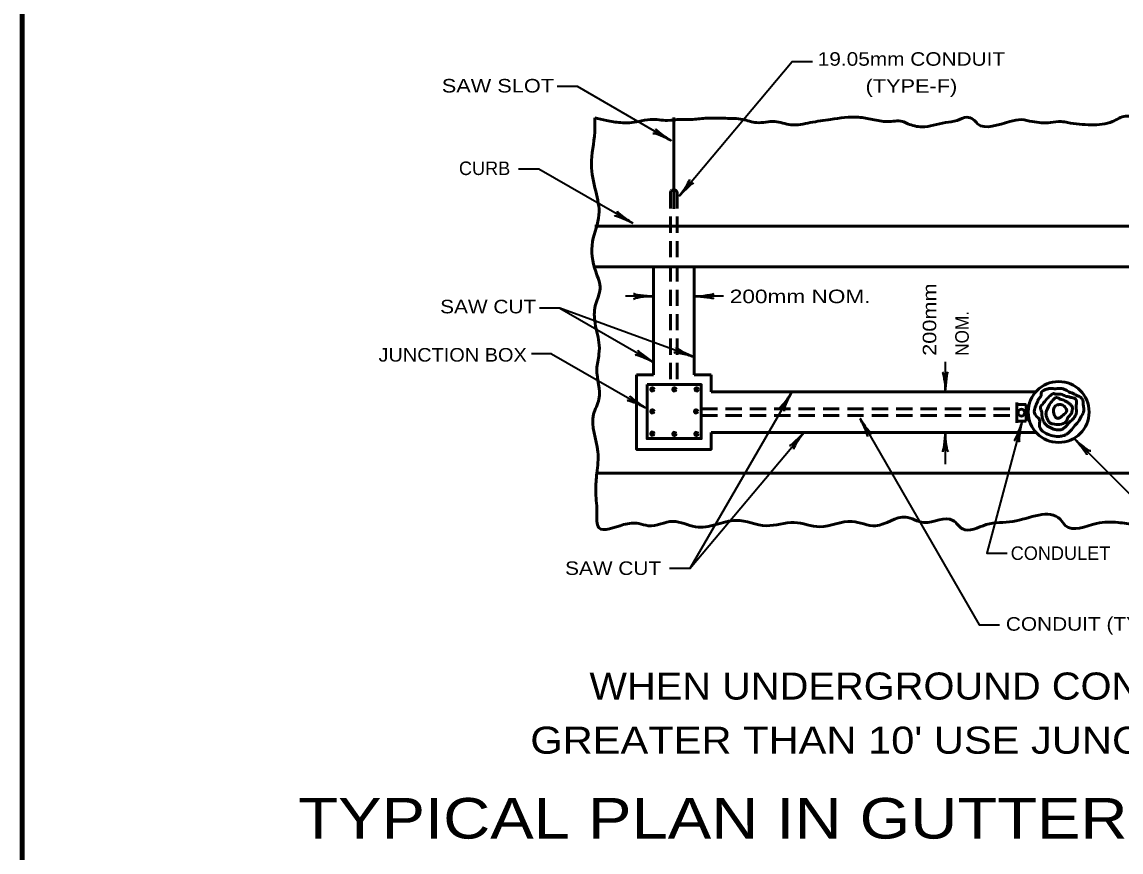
# Model space of a CAD drawing. Extents: x -90 to 623, y -379 to 75.
# Drawn here: x -42.6 to 119.8, y -254.8 to -132.1 of the extents above; entities that cross this region are included whole.
import ezdxf
from ezdxf.enums import TextEntityAlignment as Align

# ---------------------------------------------------------------- set-up
doc = ezdxf.new("R2010")
doc.units = 0
doc.header["$LTSCALE"] = 0.8
doc.linetypes.add('LONG_DASHED', pattern=[7.5, 6, -1.5])
doc.linetypes.add('MEDIUM_DASHED', pattern=[4.5, 3, -1.5])
doc.layers.add('1', color=7, linetype='Continuous', lineweight=35)

msp = doc.modelspace()

# ---------------------------------------------------------------- linework, layer by layer
at = {"layer": '1', "lineweight": 53}
for p, q in [((53.7427, -159.7717), (53.7427, -146.2717)), ((42.0595, -162.3067), (142.0595, -162.3067)), ((42.0595, -168.3067), (142.0595, -168.3067)), ((50.7427, -168.3067), (50.7427, -184.3067)), ((56.7427, -168.3067), (56.7427, -184.3067)), ((50.7427, -184.3067), (48.2427, -184.3067)), ((56.7427, -184.3067), (59.2427, -184.3067)), ((59.2427, -184.3067), (59.2427, -186.8067)), ((59.2427, -186.8067), (107.227, -186.8067)), ((104.3797, -188.6473), (105.8, -188.6473)), ((104.418, -188.3786), (104.418, -191.3786)), ((105.8, -188.6473), (105.8, -191.1473)), ((104.3797, -191.1473), (105.8, -191.1473)), ((59.2427, -192.8067), (93.8582, -192.8067)), ((93.779, -192.8067), (107.2712, -192.8067)), ((42.3769, -198.8067), (142.0708, -198.8067))]:
    msp.add_line(p, q, dxfattribs=at)
at = {"layer": '1', "linetype": 'MEDIUM_DASHED', "lineweight": 53}
for p, q in [((53.2427, -157.3067), (53.2427, -185.7174)), ((54.2427, -157.3067), (54.2427, -185.7174)), ((57.7928, -189.3067), (104.3989, -189.3067)), ((57.7928, -190.3067), (104.4088, -190.3067))]:
    msp.add_line(p, q, dxfattribs=at)
at = {"layer": '1'}
for p, q in [((50.6812, -172.6817), (46.602, -172.6817)), ((61.102, -172.6817), (56.7814, -172.6817)), ((36.8893, -174.4334), (33.8893, -174.4334)), ((35.701, -181.1674), (32.701, -181.1674)), ((35.701, -181.1674), (49.5574, -189.1674)), ((93.8582, -182.3864), (93.8582, -186.7438)), ((93.8582, -192.7647), (93.8582, -197.5024)), ((56.1208, -212.9046), (53.1208, -212.9046))]:
    msp.add_line(p, q, dxfattribs=at)
at = {"layer": '1', "lineweight": 158}
msp.add_lwpolyline([(617.1938, 69.4188), (-42.5562, 69.3355), (-42.4728, -368.9978)], dxfattribs=at)
at = {"layer": '1'}
for points in [[(54.5286, -157.8822), (71.241, -137.9651), (74.241, -137.9651)], [(53.3747, -149.6886), (39.5183, -141.6886), (36.5183, -141.6886)], [(47.6707, -161.889), (33.8143, -153.889), (30.8142, -153.889)], [(56.6229, -181.6158), (36.8893, -174.4334), (50.7458, -182.4334)], [(71.1208, -186.9238), (56.1208, -212.9046), (72.9849, -192.8067)], [(81.2615, -190.7265), (98.8817, -221.2457), (101.8817, -221.2457)], [(105.1616, -191.3462), (99.9852, -210.6647), (102.9852, -210.6647)], [(113.0107, -193.8116), (129.4815, -210.2824), (132.4815, -210.2824)]]:
    msp.add_lwpolyline(points, dxfattribs=at)
at = {"layer": '1', "lineweight": 53}
msp.add_lwpolyline([(48.2427, -184.3067), (48.2427, -195.3067), (59.2427, -195.3067), (59.2427, -192.8067)], dxfattribs=at)
msp.add_lwpolyline([(49.7928, -185.7174), (57.7928, -185.7174), (57.7928, -193.7174), (49.7928, -193.7174)], close=True, dxfattribs=at)
for centre, radius in [((50.5838, -186.4463), 0.25), ((53.8318, -186.4463), 0.25), ((57.1194, -186.4463), 0.25), ((110.6031, -189.7819), 4.5), ((50.5838, -189.6942), 0.25), ((57.0402, -189.6942), 0.25), ((105.1089, -189.8757), 0.5), ((50.5838, -192.9818), 0.25), ((53.8318, -193.0215), 0.25), ((57.0797, -193.0215), 0.25)]:
    msp.add_circle(centre, radius, dxfattribs=at)
at = {"layer": '1', "linetype": 'LONG_DASHED', "lineweight": 53}
msp.add_arc((53.7427, -157.4507), 0.5203, 16.07383, 163.92617, dxfattribs=at)
at = {"layer": '1', "lineweight": 40}
for centre, major_axis, ratio, start_param, end_param in [((52.2916, -149.3823), (1.6245, -0.7576), 0.122415, 0.89635335, 3.14159265), ((52.2916, -149.3823), (1.6245, -0.7576), 0.122415, 0.89635335, 3.14159265), ((52.5102, -148.9451), (1.4333, -1.0303), 0.07063, 3.14071475, 5.41810995), ((52.5102, -148.9451), (1.4333, -1.0303), 0.07063, 3.14071475, 5.41810995), ((55.0183, -156.8687), (-1.0282, -1.4683), 0.122415, 0.89635335, 3.14159265), ((55.0183, -156.8687), (-1.0282, -1.4683), 0.122415, 0.89635335, 3.14159265), ((55.4109, -157.1599), (1.2636, 1.2326), 0.07063, 6.28230741, 8.55970261), ((55.4109, -157.1599), (1.2636, 1.2326), 0.07063, 6.28230741, 8.55970261), ((46.5875, -161.5827), (1.6245, -0.7576), 0.122415, 0.89635335, 3.14159265), ((46.5875, -161.5827), (1.6245, -0.7576), 0.122415, 0.89635335, 3.14159265), ((46.8061, -161.1455), (1.4333, -1.0303), 0.07063, 3.14071475, 5.41810995), ((46.8061, -161.1455), (1.4333, -1.0303), 0.07063, 3.14071475, 5.41810995), ((49.59, -172.958), (1.7857, 0.1562), 0.122415, 0.89635335, 3.14159265), ((49.59, -172.958), (1.7857, 0.1562), 0.122415, 0.89635335, 3.14159265), ((49.5607, -172.4701), (1.7565, -0.1757), 0.07063, 3.14071475, 5.41810995), ((49.5607, -172.4701), (1.7565, -0.1757), 0.07063, 3.14071475, 5.41810995), ((57.9019, -172.8933), (1.7565, -0.1757), 0.07063, 6.28230741, 8.55970261), ((57.9019, -172.8933), (1.7565, -0.1757), 0.07063, 6.28230741, 8.55970261), ((57.8726, -172.4054), (-1.7857, -0.1562), 0.122415, 0.89635335, 3.14159265), ((57.8726, -172.4054), (-1.7857, -0.1562), 0.122415, 0.89635335, 3.14159265), ((49.6626, -182.1271), (1.6245, -0.7576), 0.122415, 0.89635335, 3.14159265), ((49.6626, -182.1271), (1.6245, -0.7576), 0.122415, 0.89635335, 3.14159265), ((49.8812, -181.6899), (1.4333, -1.0303), 0.07063, 3.14071475, 5.41810995), ((49.8812, -181.6899), (1.4333, -1.0303), 0.07063, 3.14071475, 5.41810995), ((55.503, -181.5023), (1.7314, -0.464), 0.122415, 0.89635335, 3.14159265), ((55.503, -181.5023), (1.7314, -0.464), 0.122415, 0.89635335, 3.14159265), ((55.6424, -181.0338), (-1.5904, 0.7658), 0.07063, 6.28230741, 8.55970261), ((55.6424, -181.0338), (-1.5904, 0.7658), 0.07063, 6.28230741, 8.55970261), ((93.5819, -185.6526), (0.1562, -1.7857), 0.122415, 0.89635335, 3.14159265), ((93.5819, -185.6526), (0.1562, -1.7857), 0.122415, 0.89635335, 3.14159265), ((94.0698, -185.6233), (0.1757, 1.7565), 0.07063, 6.28230741, 8.55970261), ((94.0698, -185.6233), (0.1757, 1.7565), 0.07063, 6.28230741, 8.55970261), ((48.4743, -188.8611), (1.6245, -0.7576), 0.122415, 0.89635335, 3.14159265), ((48.4743, -188.8611), (1.6245, -0.7576), 0.122415, 0.89635335, 3.14159265), ((48.6928, -188.4239), (1.4333, -1.0303), 0.07063, 3.14071475, 5.41810995), ((48.6928, -188.4239), (1.4333, -1.0303), 0.07063, 3.14071475, 5.41810995), ((70.3773, -187.7884), (1.0303, 1.4333), 0.07063, 3.14071475, 5.41810995), ((70.3773, -187.7884), (1.0303, 1.4333), 0.07063, 3.14071475, 5.41810995), ((70.8145, -188.007), (0.7576, 1.6245), 0.122415, 0.89635335, 3.14159265), ((70.8145, -188.007), (0.7576, 1.6245), 0.122415, 0.89635335, 3.14159265), ((81.6385, -191.8027), (-0.7261, 1.609), 0.07063, 3.14071475, 5.41810995), ((81.6385, -191.8027), (-0.7261, 1.609), 0.07063, 3.14071475, 5.41810995), ((82.0464, -191.5334), (-1.0281, 1.4684), 0.122415, 0.89635335, 3.14159265), ((82.0464, -191.5334), (-1.0281, 1.4684), 0.122415, 0.89635335, 3.14159265), ((104.6672, -192.3738), (-0.6243, -1.6511), 0.07063, 6.28230741, 8.55970261), ((104.6672, -192.3738), (-0.6243, -1.6511), 0.07063, 6.28230741, 8.55970261), ((105.146, -192.4718), (0.3113, 1.7653), 0.122415, 0.89635335, 3.14159265), ((105.146, -192.4718), (0.3113, 1.7653), 0.122415, 0.89635335, 3.14159265), ((72.1026, -193.529), (-1.2636, -1.2326), 0.07063, 6.28230741, 8.55970261), ((72.1026, -193.529), (-1.2636, -1.2326), 0.07063, 6.28230741, 8.55970261), ((72.4952, -193.8202), (1.0282, 1.4683), 0.122415, 0.89635335, 3.14159265), ((72.4952, -193.8202), (1.0282, 1.4683), 0.122415, 0.89635335, 3.14159265), ((93.6466, -193.8852), (-0.1757, -1.7565), 0.07063, 6.28230741, 8.55970261), ((93.6466, -193.8852), (-0.1757, -1.7565), 0.07063, 6.28230741, 8.55970261), ((94.1345, -193.8559), (-0.1562, 1.7857), 0.122415, 0.89635335, 3.14159265), ((94.1345, -193.8559), (-0.1562, 1.7857), 0.122415, 0.89635335, 3.14159265), ((113.6534, -194.7535), (1.1178, -1.3662), 0.07063, 6.28230741, 8.55970261), ((113.6534, -194.7535), (1.1178, -1.3662), 0.07063, 6.28230741, 8.55970261), ((113.9776, -194.3878), (-1.3731, 1.1523), 0.122415, 0.89635335, 3.14159265), ((113.9776, -194.3878), (-1.3731, 1.1523), 0.122415, 0.89635335, 3.14159265)]:
    msp.add_ellipse(centre, major_axis=major_axis, ratio=ratio, start_param=start_param, end_param=end_param, dxfattribs=at)
at = {"layer": '1', "lineweight": 53}
for points in [[(105.117, -146.5359), (106.7013, -146.8528), (109.3948, -147.0112), (110.9792, -146.8528), (111.9297, -147.0112), (115.4153, -147.3282), (118.5841, -146.8528), (120.4853, -146.0607), (122.2281, -146.3775), (126.6643, -146.3775), (128.724, -146.8528), (129.0408, -147.0112), (130.7837, -146.2191), (131.1005, -147.3282), (134.1108, -147.1697), (136.3289, -146.5359), (137.1211, -147.0112), (139.1807, -147.4866), (141.5573, -145.4269), (141.8742, -146.2191), (141.7157, -148.2788), (141.8742, -150.6553), (141.7157, -154.2993), (142.1911, -156.5174), (142.0327, -157.9433), (142.5079, -161.7458), (142.5079, -164.1223), (142.3495, -166.3405), (142.1911, -168.2417), (141.8742, -170.6182), (141.3989, -172.9948), (141.3989, -175.6882), (141.7157, -177.7479), (141.5573, -179.6491), (142.8248, -181.075), (142.3495, -183.1347), (142.0327, -185.9866), (142.3495, -188.8384), (142.3495, -190.5812), (142.0327, -193.7499), (142.5079, -194.5421), (141.8742, -196.7602), (142.0327, -198.9783), (141.3989, -201.8302), (141.8742, -203.4145), (142.3495, -205.9495), (141.082, -206.2664), (138.3886, -206.5832), (136.8042, -205.9495), (133.9524, -206.1079), (131.7343, -205.9495), (129.5162, -206.4248), (127.7733, -205.3157), (124.6047, -206.2664), (121.9112, -206.4248), (119.3762, -206.1079), (116.2075, -206.2664), (111.6129, -206.5832), (110.8207, -205.6327), (103.8495, -205.9495), (99.8886, -206.4248), (96.403, -207.0586), (94.9771, -205.7911), (90.6993, -206.1079), (88.0059, -205.3157), (83.5697, -206.5832), (80.0841, -205.9495), (75.331, -206.7417), (71.5285, -206.1079), (67.4092, -206.5832), (62.973, -205.7911), (59.9627, -206.4248), (56.9524, -206.7417), (53.6253, -205.9495), (49.9812, -206.5832), (48.5553, -206.2664), (46.3372, -206.4248), (42.6932, -206.9002), (42.3762, -204.5236), (42.2178, -201.3548), (42.3762, -198.8199), (42.5347, -195.6512), (41.901, -190.1059), (42.6932, -187.8877), (42.3762, -183.4516), (42.6932, -181.2335), (42.6932, -179.4907), (42.0594, -176.3219), (42.2178, -173.787), (42.8516, -171.5688), (42.2178, -169.0339), (41.7425, -164.5977), (42.6932, -160.6368), (42.2178, -157.1512), (41.5841, -153.1902), (42.0594, -148.4372), (42.0595, -146.3067)], [(42.0595, -146.3067), (43.8023, -146.6944), (45.8619, -147.0112), (48.5553, -146.8528), (50.2981, -146.5359), (52.8331, -146.6944), (54.7343, -146.5359), (56.3187, -146.5359), (58.3783, -146.3775), (61.3886, -146.3775), (63.9236, -146.5359), (65.9832, -147.0112), (68.6767, -146.8528), (71.0532, -147.3282), (73.9051, -147.0112), (76.9153, -146.5359), (81.0347, -146.2191), (83.0944, -146.5359), (85.3125, -146.8528), (87.5306, -146.8528), (88.3227, -147.1697), (90.3824, -147.645), (93.868, -147.0112), (95.6108, -146.6944), (97.0367, -146.2191), (97.9874, -146.5359), (98.6211, -147.1697), (103.3742, -146.8528), (105.117, -146.5359)], [(108.5777, -186.5185), (108.0628, -186.875), (108.0034, -187.39), (107.6469, -187.8851), (107.4687, -188.2614), (107.132, -189.0734), (107.0132, -189.4695), (107.2706, -190.3607), (107.7262, -190.7767), (107.7856, -191.6481), (108.0034, -192.4007), (108.4986, -192.8167), (109.4888, -193.2326), (110.5583, -193.391), (111.1921, -193.292), (111.9645, -192.9355), (112.5587, -192.3611), (113.1726, -191.5887), (113.747, -190.8559), (113.945, -190.4202), (114.2619, -189.8458), (114.3213, -189.3705), (114.2421, -188.6972), (114.1034, -187.8653), (113.6876, -187.5088), (113.2717, -187.3306), (112.9349, -187.1325), (112.1229, -186.7958), (111.4693, -186.4393), (111.0733, -186.3007), (110.3998, -186.3205), (109.9443, -186.3402), (109.4096, -186.3007), (108.9145, -186.3799), (108.6768, -186.4393), (108.4392, -186.5582)], [(109.568, -187.1919), (108.8748, -187.8257), (108.2015, -188.6575), (107.9044, -189.2121), (108.0827, -189.6478), (108.1421, -190.2618), (108.2807, -190.9153), (108.5382, -191.4303), (108.8947, -191.8263), (109.2512, -192.0244), (110.083, -192.3809), (110.4791, -192.4205), (110.9148, -192.4205), (111.2911, -192.2225), (111.6476, -191.9254), (112.0635, -191.4303), (112.5388, -190.9946), (112.7171, -190.8361), (113.133, -190.1825), (113.232, -189.7072), (113.1726, -188.9546), (113.232, -188.1822), (113.0736, -187.8257), (112.7171, -187.6672), (112.3804, -187.6277), (112.1427, -187.5484), (111.7862, -187.4692), (111.1128, -187.2117), (110.7366, -187.1325), (110.2018, -187.1523), (109.7859, -187.0532), (109.4888, -187.2513)], [(110.0632, -187.7267), (109.469, -188.3802), (108.8154, -189.628), (108.7362, -190.2023), (109.0135, -190.9352), (109.3106, -191.3907), (109.7265, -191.5491), (110.7167, -191.6283), (111.7268, -191.1728), (111.9843, -190.5787), (112.4794, -189.9845), (112.6181, -189.4695), (112.5982, -188.9942), (112.3012, -188.6377), (111.9248, -188.3407), (111.5288, -188.1227), (111.2119, -187.9842), (110.8356, -187.9049), (110.6178, -187.7465), (110.3008, -187.6277), (109.9839, -187.7465)], [(110.4395, -188.6773), (109.9443, -189.113), (109.8453, -189.7072), (109.9443, -190.1627), (110.083, -190.4202), (110.2612, -190.6182), (110.4989, -190.7173), (110.9742, -190.4796), (111.2515, -190.2222), (111.7664, -189.7072), (111.7862, -189.4299), (111.6277, -189.1527), (111.4099, -188.8952), (111.0534, -188.7169), (110.7762, -188.6575), (110.5781, -188.6773), (110.3801, -188.8159)]]:
    msp.add_spline(points, degree=3, dxfattribs=at)

# ---------------------------------------------------------------- texts
at = {"layer": '1'}
for s, height, width, p in [('19.05mm CONDUIT', 2, 1.15, (88.8516, -138.6042)), ('(TYPE-F)', 2, 1.2, (88.8515, -142.6042)), ('WHEN UNDERGROUND CONDUIT IS', 4, 1.1, (92.4321, -232.2779)), ("GREATER THAN 10' USE JUNCTION BOX", 4, 1.15, (92.4321, -240.2779))]:
    msp.add_text(s, height=height, dxfattribs=dict(at, width=width)).set_placement(p, align=Align.CENTER)
for s, height, width, p in [('SAW SLOT', 2, 1.2, (19.4669, -142.5584)), ('200mm NOM.', 2, 1.25, (62.0101, -173.6934)), ('SAW CUT', 2, 1.15, (19.2293, -175.1987)), ('JUNCTION BOX', 2, 1.1, (10.1186, -182.3288)), ('SAW CUT', 2, 1.15, (37.6883, -213.8599)), ('CONDUIT (TYPE-R)', 2, 1.15, (102.8104, -222.0992)), ('TYPICAL PLAN IN GUTTER AND SIDEWALK', 6, 1.2, (-1.7292, -252.8244))]:
    msp.add_text(s, height=height, dxfattribs=dict(at, width=width)).set_placement(p)
for s, p in [('CURB', (22.0021, -154.7589)), ('CONDULET', (103.5234, -211.6417))]:
    msp.add_text(s, height=2, dxfattribs=at).set_placement(p)
for s, width, p in [('200mm', 1.2, (92.5242, -181.4783)), ('NOM.', 0.95, (97.3242, -181.4783))]:
    msp.add_text(s, height=2, rotation=90, dxfattribs=dict(at, width=width)).set_placement(p)

doc.saveas('drawing.dxf')
